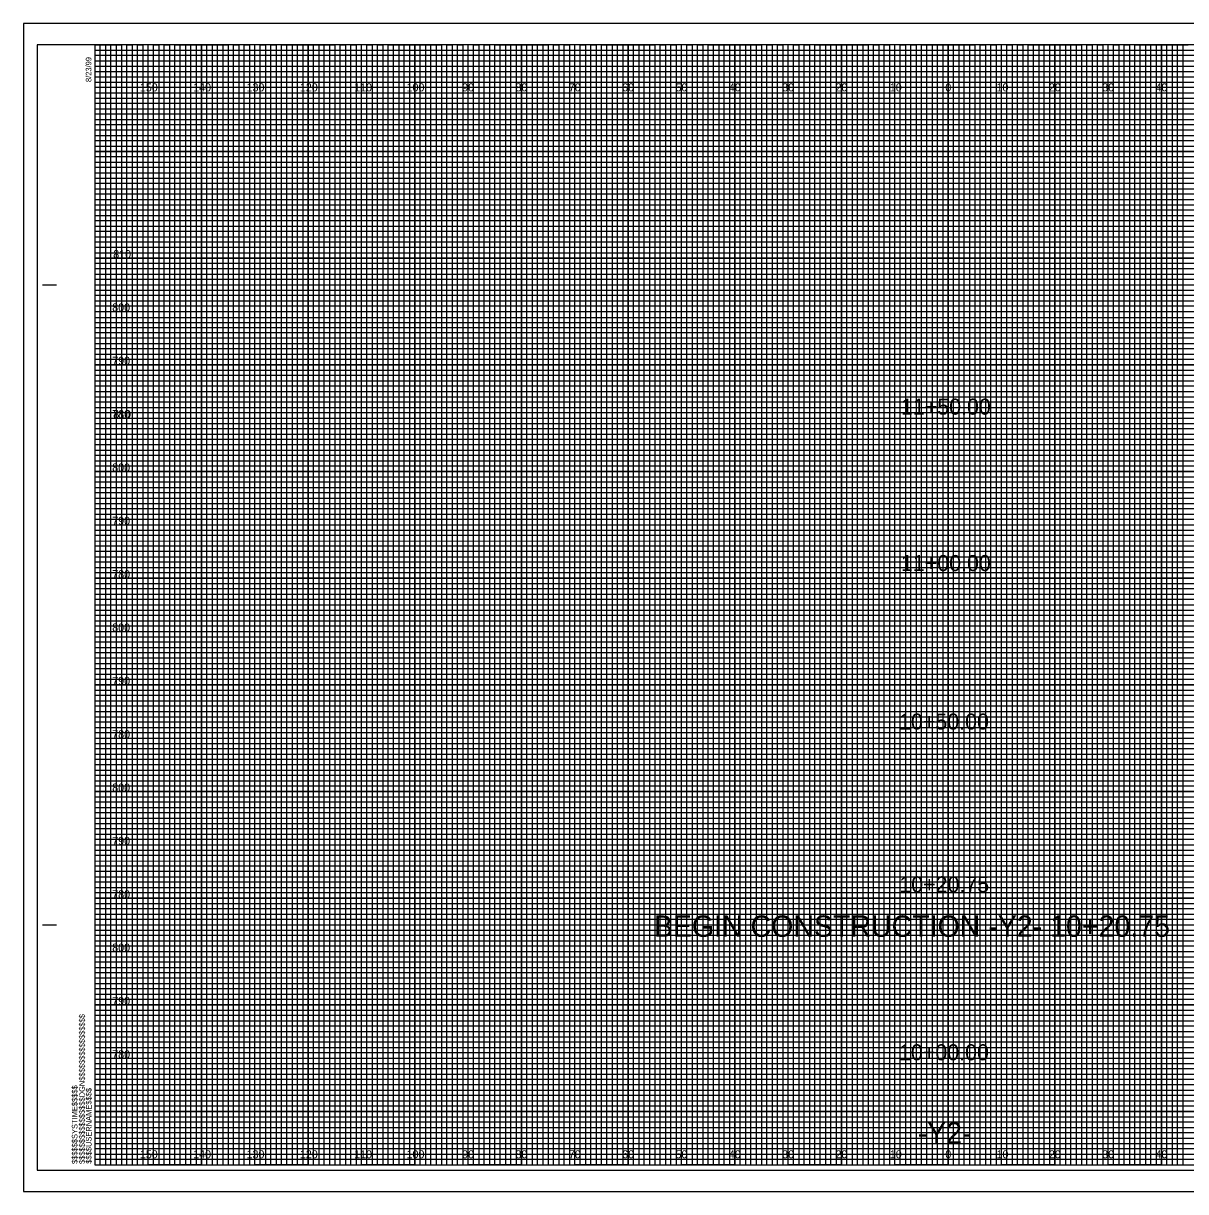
# Model space of a CAD drawing. Extents: x -13 to 323, y -5 to 214.
# Drawn here: x -13.4 to 204.5, y -5 to 214 of the extents above; entities that cross this region are included whole.
import ezdxf

# ---------------------------------------------------------------- set-up
doc = ezdxf.new("R2010")
doc.units = 0
for name, color, linetype in [('Prop XS Alignment Label', 7, 'Continuous'), ('Prop XS Elevation Labels', 7, 'Continuous'), ('Prop XS Offset Labels', 7, 'Continuous'), ('Prop XS Station Labels', 7, 'Continuous'), ('Sheet Cross Section CELL', 7, 'Continuous'), ('Sheet Cross Section Grid Major CELL', 7, 'Continuous'), ('Sheet Cross Section Grid Middle CELL', 7, 'Continuous'), ('Sheet Cross Section Grid Minor 1 CELL', 7, 'Continuous'), ('Sheet Cross Section Grid Minor 2 CELL', 7, 'Continuous'), ('Sheet Cutting Line CELL', 7, 'Continuous'), ('Sheet DOT Grid CELL', 7, 'Continuous'), ('Sheet Plot Border Inside CELL', 7, 'Continuous'), ('Sheet Plot Border Outside CELL', 7, 'Continuous')]:
    doc.layers.add(name, color=color, linetype=linetype)

msp = doc.modelspace()

# ---------------------------------------------------------------- linework, layer by layer
at = {"layer": 'Sheet Cross Section CELL'}
for p, q in [((-9.8, 165), (-7.3, 165)), ((-9.7, 165), (-7.2, 165)), ((-9.8, 45), (-7.3, 45)), ((-9.7, 45), (-7.2, 45)), ((0, 0), (0, 0)), ((0, 0), (0, 0)), ((0, 0), (0, 0)), ((0, 0), (0, 0)), ((0, 0), (0, 0)), ((0, 0), (0, 0)), ((0, 0), (0, 0))]:
    msp.add_line(p, q, dxfattribs=at)
msp.add_lwpolyline([(320, 210), (0, 210), (0, 0), (320, 0)], close=True, dxfattribs=at)
at = {"layer": 'Sheet Cross Section Grid Major CELL'}
for p, q in [((10, 210), (0, 210)), ((10, 0), (10, 210)), ((30, 210), (20, 210)), ((20, 210), (20, 0)), ((30, 0), (30, 210)), ((50, 210), (40, 210)), ((40, 210), (40, 0)), ((50, 0), (50, 210)), ((70, 210), (60, 210)), ((60, 210), (60, 0)), ((70, 0), (70, 210)), ((90, 210), (80, 210)), ((80, 210), (80, 0)), ((90, 0), (90, 210)), ((110, 210), (100, 210)), ((100, 210), (100, 0)), ((110, 0), (110, 210)), ((130, 210), (120, 210)), ((120, 210), (120, 0)), ((130, 0), (130, 210)), ((150, 210), (140, 210)), ((140, 210), (140, 0)), ((150, 0), (150, 210)), ((170, 210), (160, 210)), ((160, 210), (160, 0)), ((170, 0), (170, 210)), ((190, 210), (180, 210)), ((180, 210), (180, 0)), ((190, 0), (190, 210)), ((210, 210), (200, 210)), ((200, 210), (200, 0)), ((20, 0), (10, 0)), ((40, 0), (30, 0)), ((60, 0), (50, 0)), ((80, 0), (70, 0)), ((100, 0), (90, 0)), ((120, 0), (110, 0)), ((140, 0), (130, 0)), ((160, 0), (150, 0)), ((180, 0), (170, 0)), ((200, 0), (190, 0))]:
    msp.add_line(p, q, dxfattribs=at)
for points in [[(0, 200), (320, 200), (320, 190), (0, 190)], [(0, 180), (320, 180), (320, 170), (0, 170)], [(0, 160), (320, 160), (320, 150), (0, 150)], [(0, 140), (320, 140), (320, 130), (0, 130)], [(0, 120), (320, 120), (320, 110), (0, 110)], [(0, 100), (320, 100), (320, 90), (0, 90)], [(0, 80), (320, 80), (320, 70), (0, 70)], [(0, 60), (320, 60), (320, 50), (0, 50)], [(0, 40), (320, 40), (320, 30), (0, 30)], [(0, 20), (320, 20), (320, 10), (0, 10)]]:
    msp.add_lwpolyline(points, dxfattribs=at)
at = {"layer": 'Sheet Cross Section Grid Middle CELL'}
for points in [[(0, 210), (5, 210), (5, 0), (15, 0), (15, 210), (25, 210), (25, 0), (35, 0), (35, 210), (45, 210), (45, 0), (55, 0), (55, 210), (65, 210), (65, 0), (75, 0), (75, 210), (85, 210), (85, 0), (95, 0), (95, 210), (105, 210), (105, 0), (115, 0), (115, 210), (125, 210), (125, 0), (135, 0), (135, 210), (145, 210), (145, 0), (155, 0), (155, 210), (165, 210), (165, 0), (175, 0), (175, 210), (185, 210), (185, 0), (195, 0), (195, 210), (205, 210)], [(0, 205), (275, 205)], [(0, 185), (320, 185), (320, 195), (0, 195)], [(0, 165), (320, 165), (320, 175), (0, 175)], [(0, 145), (320, 145), (320, 155), (0, 155)], [(0, 125), (320, 125), (320, 135), (0, 135)], [(0, 105), (320, 105), (320, 115), (0, 115)], [(0, 85), (320, 85), (320, 95), (0, 95)], [(0, 65), (320, 65), (320, 75), (0, 75)], [(0, 45), (320, 45), (320, 55), (0, 55)], [(0, 25), (320, 25), (320, 35), (0, 35)], [(0, 5), (320, 5), (320, 15), (0, 15)]]:
    msp.add_lwpolyline(points, dxfattribs=at)
at = {"layer": 'Sheet Cross Section Grid Minor 1 CELL'}
for p, q in [((0, 209), (260, 209)), ((260, 207.98), (0, 207.98)), ((0, 207.98), (0, 207)), ((0, 207), (260, 207)), ((260, 205.89), (0, 205.89)), ((0, 205.89), (0, 204)), ((0, 204), (320, 204))]:
    msp.add_line(p, q, dxfattribs=at)
for points in [[(0, 203), (270, 203), (320, 203), (320, 202), (0, 202)], [(0, 201), (320, 201), (320, 199), (0, 199)], [(0, 198), (320, 198), (320, 197), (0, 196.98)], [(0, 196), (320, 196), (320, 194), (0, 194)], [(0, 193), (320, 193), (320, 192), (0, 192)], [(0, 191), (320, 191), (320, 189), (0, 189)], [(0, 188), (320, 188), (320, 187), (0, 187)], [(0, 186), (320, 186), (320, 184), (0, 184)], [(0, 183), (320, 183), (320, 182), (0, 182)], [(0, 181), (320, 181), (320, 179), (0, 179)], [(0, 178), (320, 178), (320, 177), (0, 177)], [(0, 176), (320, 176), (320, 173.95), (320, 173), (320, 172), (0, 172)], [(0, 174), (320, 174), (320, 173), (0, 173)], [(0, 171), (320, 171), (320, 169), (0, 169.03)], [(0, 169.03), (320, 169), (320, 168), (0, 168)], [(0, 167), (320, 167), (320, 166), (0, 166)], [(0, 164), (320, 164), (320, 163), (0, 163)], [(0, 162), (320, 162), (320, 161), (0, 161)], [(-0.07, 158.89), (320, 158.89), (320, 157.88), (-0.07, 157.88)], [(0, 157), (320, 157), (320, 156), (0, 156)], [(0, 154), (320, 154), (320, 153), (0, 153)], [(0, 152), (320, 152), (320, 151), (0, 151)], [(0, 149), (320, 149), (320, 148), (0, 148)], [(0, 147), (320, 147), (320, 146), (0, 146)], [(0, 144), (320, 144), (320, 143), (0, 143)], [(0, 142), (320, 142), (320, 141), (0, 141)], [(0, 139), (320, 139), (319.99, 137.98), (0, 138)], [(0, 137), (320, 137), (320, 136), (0, 136)], [(0, 134), (320, 134), (320, 133), (0, 133)], [(0, 132), (320, 132), (320, 131), (0, 131)], [(0, 129), (320, 129), (320, 128), (0, 128)], [(0, 127), (320, 127), (320, 126), (0, 126)], [(0, 124), (320, 124), (320, 123), (0, 123)], [(0, 122), (320, 122), (320, 121), (0, 121)], [(0, 119), (320, 119), (320, 118), (0, 118)], [(0, 116.99), (320.07, 116.91), (320, 116), (0, 116)], [(0, 114), (320, 114), (320, 113), (0, 113)], [(0, 112), (320, 112), (320, 111), (0, 111)], [(0, 109), (320, 109), (320, 108), (0, 108)], [(0, 107), (320, 107), (320, 106), (0, 106)], [(0, 104), (320, 104), (320, 103), (0, 103)], [(0, 102), (320, 102), (320, 101), (0, 101)], [(0, 99), (320, 99), (320, 98), (0, 98)], [(0, 97), (320, 97), (320, 96), (0, 96)], [(0, 94), (320, 94), (320, 93), (0, 93)], [(0, 92), (320, 92), (320, 91), (0, 91)], [(0, 89), (320, 89), (320, 88), (0, 88)], [(0, 87), (320, 87), (320, 86), (0, 86)], [(0, 84), (320, 84), (320, 83), (0, 83)], [(0, 82), (320, 82), (320, 81), (0, 81)], [(0, 79), (320, 79), (319.99, 77.98), (0, 78)], [(0, 77), (320, 77), (320, 76), (0, 76)], [(0, 74), (320, 74), (320, 73), (0, 73)], [(0, 72), (320, 72), (320, 71), (0, 71)], [(0, 69), (320, 69), (320, 68), (0, 68)], [(0, 67), (320, 67), (320, 66), (0, 66)], [(0, 64), (320, 64), (320, 63), (0, 63)], [(0, 62), (320, 62), (320, 61), (0, 61)], [(0, 59), (320, 59), (320, 58), (0, 58)], [(0, 56.99), (320.07, 56.91), (320, 56), (0, 56)], [(0, 54), (320, 54), (320, 53), (0, 53)], [(0, 52), (320, 52), (320, 51), (0, 51)], [(0, 49), (320, 49), (320, 48), (0, 48)], [(0, 47), (320, 47), (320, 46), (0, 46)], [(0, 44), (320, 44), (320, 43), (0, 43)], [(0, 42), (320, 42), (320, 41), (0, 41)], [(0, 39), (320, 39), (320, 38), (0, 38)], [(0, 37), (320, 37), (320, 36), (0, 36)], [(0, 34), (320, 34), (320, 33), (0, 33)], [(0, 32), (320, 32), (320, 31), (0, 31)], [(0, 29), (320, 29), (320, 28), (0, 28)], [(0, 27), (320, 27), (320, 26), (0, 26)], [(0, 24), (320, 24), (320, 23), (0, 23)], [(0, 22), (320, 22), (320, 21), (0, 21)], [(0, 19), (320, 19), (320, 18), (0, 18)], [(0, 17), (320, 17), (320, 16), (0, 16)], [(0, 14), (320, 14), (320, 13), (0, 13)], [(0, 12), (320, 12), (320, 11), (0, 11)], [(0, 9), (320, 9), (320, 8), (0, 8)], [(0, 7), (320, 7), (320, 6), (0, 6)], [(0, 4), (320, 4), (320, 3), (0, 3)], [(0, 2), (320, 2), (320, 1), (0, 1)]]:
    msp.add_lwpolyline(points, dxfattribs=at)
at = {"layer": 'Sheet Cross Section Grid Minor 2 CELL'}
for points in [[(0, 0), (1, 0), (1, 210), (2, 210), (2, 0)], [(2, 0), (3, 0), (3, 210), (4, 210), (4, 0)], [(5, 0), (6, 0), (6, 210), (7, 210), (7, 0)], [(7, 0), (8, 0), (8, 210), (9, 210), (9, 0)], [(10, 0), (11, 0), (11, 210), (12, 210), (12, 0)], [(12, 0), (13, 0), (13, 210), (14, 210), (14, 0)], [(15, 0), (16, 0), (16, 210), (17, 210), (17, 0)], [(17, 0), (18, 0), (18, 210), (19, 210), (19, 0)], [(20, 0), (21, 0), (21, 210), (22, 210), (22, 0)], [(22, 0), (23, 0), (23, 210), (24, 210), (24, 0)], [(25, 0), (26, 0), (26, 210), (27, 210), (27, 0)], [(27, 0), (28, 0), (28, 210), (29, 210), (29, 0)], [(30, 0), (31, 0), (31, 210), (32, 210), (32, 0)], [(32, 0), (33, 0), (33, 210), (34, 210), (34, 0)], [(35, 0), (36, 0), (36, 210), (37, 210), (37, 0)], [(37, 0), (38, 0), (38, 210), (39, 210), (39, 0)], [(40, 0), (41, 0), (41, 210), (42, 210), (42, 0)], [(42, 0), (43, 0), (43, 210), (44, 210), (44, 0)], [(45, 0), (46, 0), (46, 210), (47, 210), (47, 0)], [(47, 0), (48, 0), (48, 210), (49, 210), (49, 0)], [(50, 0), (51, 0), (51, 210), (52, 210), (52, 0)], [(52, 0), (53, 0), (53, 210), (54, 210), (54, 0)], [(55, 0), (56, 0), (56, 210), (57, 210), (57, 0)], [(57, 0), (58, 0), (58, 210), (59, 210), (59, 0)], [(60, 0), (61, 0), (61, 210), (62, 210), (62, 0)], [(62, 0), (63, 0), (63, 210), (64, 210), (64, 0)], [(65, 0), (66, 0), (66, 210), (67, 210), (67, 0)], [(67, 0), (68, 0), (68, 210), (69, 210), (69, 0)], [(70, 0), (71, 0), (71, 210), (72, 210), (72, 0)], [(72, 0), (73, 0), (73, 210), (74, 210), (74, 0)], [(75, 0), (76, 0), (76, 210), (77, 210), (77, 0)], [(77, 0), (78, 0), (78, 210), (79, 210), (79, 0)], [(80, 0), (81, 0), (81, 210), (82, 210), (82, 0)], [(82, 0), (83, 0), (83, 210), (84, 210), (84, 0)], [(85, 0), (86, 0), (86, 210), (87, 210), (87, 0)], [(87, 0), (88, 0), (88, 210), (89, 210), (89, 0)], [(90, 0), (91, 0), (91, 210), (92, 210), (92, 0)], [(92, 0), (93, 0), (93, 210), (94, 210), (94, 0)], [(95, 0), (96, 0), (96, 210), (97, 210), (97, 0)], [(97, 0), (98, 0), (98, 210), (99, 210), (99, 0)], [(100, 0), (101, 0), (101, 210), (102, 210), (102, 0)], [(102, 0), (103, 0), (103, 210), (104, 210), (104, 0)], [(105, 0), (106, 0), (106, 210), (107, 210), (107, 0)], [(107, 0), (108, 0), (108, 210), (109, 210), (109, 0)], [(110, 0), (111, 0), (111, 210), (112, 210), (112, 0)], [(112, 0), (113, 0), (113, 210), (114, 210), (114, 0)], [(115, 0), (116, 0), (116, 210), (117, 210), (117, 0)], [(117, 0), (118, 0), (118, 210), (119, 210), (119, 0)], [(120, 0), (121, 0), (121, 210), (122, 210), (122, 0)], [(122, 0), (123, 0), (123, 210), (124, 210), (124, 0)], [(125, 0), (126, 0), (126, 210), (127, 210), (127, 0)], [(127, 0), (128, 0), (128, 210), (129, 210), (129, 0)], [(130, 0), (131, 0), (131, 210), (132, 210), (132, 0)], [(132, 0), (133, 0), (133, 210), (134, 210), (134, 0)], [(135, 0), (136, 0), (136, 210), (137, 210), (137, 0)], [(137, 0), (138, 0), (138, 210), (139, 210), (139, 0)], [(140, 0), (141, 0), (141, 210), (142, 210), (142, 0)], [(142, 0), (143, 0), (143, 210), (144, 210), (144, 0)], [(145, 0), (146, 0), (146, 210), (147, 210), (147, 0)], [(147, 0), (148, 0), (148, 210), (149, 210), (149, 0)], [(150, 0), (151, 0), (151, 210), (152, 210), (152, 0)], [(152, 0), (153, 0), (153, 210), (154, 210), (154, 0)], [(155, 0), (156, 0), (156, 210), (157, 210), (157, 0)], [(157, 0), (158, 0), (158, 210), (159, 210), (159, 0)], [(160, 0), (161, 0), (161, 210), (162, 210), (162, 0)], [(162, 0), (163, 0), (163, 210), (164, 210), (164, 0)], [(165, 0), (166, 0), (166, 210), (167, 210), (167, 0)], [(167, 0), (168, 0), (168, 210), (169, 210), (169, 0)], [(170, 0), (171, 0), (171, 210), (172, 210), (172, 0)], [(172, 0), (173, 0), (173, 210), (174, 210), (174, 0)], [(175, 0), (176, 0), (176, 210), (177, 210), (177, 0)], [(177, 0), (178, 0), (178, 210), (179, 210), (179, 0)], [(180, 0), (181, 0), (181, 210), (182, 210), (182, 0)], [(182, 0), (183, 0), (183, 210), (184, 210), (184, 0)], [(185, 0), (186, 0), (186, 210), (187, 210), (187, 0)], [(187, 0), (188, 0), (188, 210), (189, 210), (189, 0)], [(190, 0), (191, 0), (191, 210), (192, 210), (192, 0)], [(192, 0), (193, 0), (193, 210), (194, 210), (194, 0)], [(195, 0), (196, 0), (196, 210), (197, 210), (197, 0)], [(197, 0), (198, 0), (198, 210), (199, 210), (199, 0)], [(200, 0), (201, 0), (201, 210), (202, 210), (202, 0)], [(202, 0), (203, 0), (203, 210), (204, 210), (204, 0)]]:
    msp.add_lwpolyline(points, dxfattribs=at)
at = {"layer": 'Sheet Cutting Line CELL'}
for p, q in [((323.3, 214), (-13.4, 214)), ((-13.4, 214), (-13.4, -5)), ((-13.4, -5), (323.3, -5))]:
    msp.add_line(p, q, dxfattribs=at)
at = {"layer": 'Sheet DOT Grid CELL'}
for p, q in [((10, 0), (10, 210)), ((20, 0), (20, 210)), ((30, 0), (30, 210)), ((40, 0), (40, 210)), ((50, 0), (50, 210)), ((60, 0), (60, 210)), ((70, 0), (70, 210)), ((80, 0), (80, 210)), ((90, 0), (90, 210)), ((100, 0), (100, 210)), ((110, 0), (110, 210)), ((120, 0), (120, 210)), ((130, 0), (130, 210)), ((140, 0), (140, 210)), ((150, 0), (150, 210)), ((160, 0), (160, 210)), ((170, 0), (170, 210)), ((180, 0), (180, 210)), ((190, 0), (190, 210)), ((200, 0), (200, 210)), ((0, 200), (320, 200)), ((0, 190), (320, 190)), ((0, 180), (320, 180)), ((0, 170), (320, 170)), ((0, 160), (320, 160)), ((0, 150), (320, 150)), ((0, 140), (320, 140)), ((0, 130), (320, 130)), ((0, 120), (320, 120)), ((0, 110), (320, 110)), ((0, 100), (320, 100)), ((0, 90), (320, 90)), ((0, 80), (320, 80)), ((0, 70), (320, 70)), ((0, 60), (320, 60)), ((0, 50), (320, 50)), ((0, 40), (320, 40)), ((0, 30), (320, 30)), ((0, 20), (320, 20)), ((0, 10), (320, 10))]:
    msp.add_line(p, q, dxfattribs=at)
at = {"layer": 'Sheet Plot Border Inside CELL'}
msp.add_lwpolyline([(-10.8, -1), (322.4, -1), (322.4, 210), (-10.8, 210)], close=True, dxfattribs=at)
at = {"layer": 'Sheet Plot Border Outside CELL'}
msp.add_lwpolyline([(-13.4, -5), (323.3, -5), (323.3, 214), (-13.4, 214)], close=True, dxfattribs=at)

# ---------------------------------------------------------------- texts
at = {"layer": 'Prop XS Alignment Label'}
for s, p in [('BEGIN CONSTRUCTION -Y2- 10+20.75', (104.8, 42.77)), ('-Y2-', (154.25, 4))]:
    msp.add_text(s, height=4, dxfattribs=at).set_placement(p)
at = {"layer": 'Prop XS Elevation Labels'}
for s, p in [('810', (3.44, 170)), ('800', (3.26, 160)), ('790', (3.26, 150)), ('780', (3.26, 140)), ('810', (3.44, 140)), ('800', (3.26, 130)), ('790', (3.26, 120)), ('780', (3.26, 110)), ('800', (3.26, 100)), ('790', (3.26, 90)), ('780', (3.26, 80)), ('800', (3.26, 70)), ('790', (3.26, 60)), ('780', (3.26, 50)), ('800', (3.26, 40)), ('790', (3.26, 30)), ('780', (3.26, 20))]:
    msp.add_text(s, height=1.5, dxfattribs=at).set_placement(p)
at = {"layer": 'Prop XS Offset Labels'}
for s, p in [('150', (8.44, 201.25)), ('140', (18.44, 201.25)), ('130', (28.44, 201.25)), ('120', (38.44, 201.25)), ('110', (48.62, 201.25)), ('100', (58.44, 201.25)), ('90', (68.86, 201.25)), ('80', (78.86, 201.25)), ('70', (88.86, 201.25)), ('60', (98.86, 201.25)), ('50', (108.86, 201.25)), ('40', (118.86, 201.25)), ('30', (128.86, 201.25)), ('20', (138.86, 201.25)), ('10', (149.04, 201.25)), ('0', (159.45, 201.25)), ('0', (159.45, 201.25)), ('10', (169.04, 201.25)), ('20', (178.86, 201.25)), ('30', (188.86, 201.25)), ('40', (198.86, 201.25)), ('150', (8.44, 1.25)), ('140', (18.44, 1.25)), ('130', (28.44, 1.25)), ('120', (38.44, 1.25)), ('110', (48.62, 1.25)), ('100', (58.44, 1.25)), ('90', (68.86, 1.25)), ('80', (78.86, 1.25)), ('70', (88.86, 1.25)), ('60', (98.86, 1.25)), ('50', (108.86, 1.25)), ('40', (118.86, 1.25)), ('30', (128.86, 1.25)), ('20', (138.86, 1.25)), ('10', (149.04, 1.25)), ('0', (159.45, 1.25)), ('0', (159.45, 1.25)), ('10', (169.04, 1.25)), ('20', (178.86, 1.25)), ('30', (188.86, 1.25)), ('40', (198.86, 1.25))]:
    msp.add_text(s, height=1.5, dxfattribs=at).set_placement(p)
at = {"layer": 'Prop XS Station Labels'}
for s, p in [('11+50.00', (151.13, 140.65)), ('11+00.00', (151.13, 111.33)), ('10+50.00', (150.77, 81.62)), ('10+20.75', (150.82, 51.1)), ('10+00.00', (150.77, 19.62))]:
    msp.add_text(s, height=3, dxfattribs=at).set_placement(p)
at = {"layer": 'Sheet Cross Section CELL'}
for s, p in [('8/23/99', (-0.65, 203)), ('$$$$$$$$$$$$$$$$DGN$$$$$$$$$$$$$$$$', (-1.88, 0.18)), ('$$$$$$SYSTIME$$$$$', (-3.26, 0.18)), ('$$$$USERNAME$$$$', (-0.62, 0.23))]:
    msp.add_text(s, height=1.05, rotation=90, dxfattribs=at).set_placement(p)

doc.saveas('drawing.dxf')
